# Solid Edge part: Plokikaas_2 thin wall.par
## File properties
Author: KULL
Template: Iso Metric Part.par
Last saved by: KULL
Revision: 9
Application: Solid Edge
Accuracy: 0,990
Face Style: Model Default
Fill Style: Normal
Coef. of Thermal Exp: 0.0
Thermal Conductivity: 0.0
Specific Heat: 0.0
Modulus of Elasticity: 0.0
Poisson's Ratio: 0.0
Yield Stress: 0.0
Ultimate Stress: 0.0
Elongation: 0.0
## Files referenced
..\..\Mootor_ASM_1.asm
hiplokk 2.par
lG:\Haapsalu Kolledz\Solid edge leong\Solid edge Sync practice\ROVER_Heiko_Kull_EKSAM\Mootor\Mootor_ASM_1.asm
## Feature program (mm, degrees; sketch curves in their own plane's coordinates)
pattern "unnamed Pattern 1"
pattern "unnamed Pattern 2"
Other named dimensions: "Pattern_1": XDirCount = 5; XDirSpacing = 18 mm | "Pattern_2": XDirCount = 5; XDirSpacing = 18 mm
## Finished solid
Body 1: sheet body, 1 face, 13 edges, 8 vertices.
  Faces by surface: plane 1
  Edges by curve: circle 9, line 4
Body 2: solid body, 256 faces, 478 edges, 216 vertices, 1 internal void.
  Faces by surface: plane 54, cylinder 52, torus 50, offset 40, spline 40, cone 20
  Edges by curve: circle 142, line 120, intersection 116, ellipse 40, curve on surface 30, spline 30
Bounding box of the edges (mm; curved faces can reach further): 96.000 x 29.454 x 27.888, from (-48, 15.1609, 37.8813) to (48, 44.6145, 65.7694).
Cylindrical faces by radius (mm): R0.7583 x10, R0.7983 x10, R3 x4, R3.04 x4, R5 x8, R5.04 x8, R7.96 x4, R8 x4
Conical faces (half-angle, radius in mm at the cone's reference point): 0.9869 deg R2.4867 x10, 0.9869 deg R2.5267 x10
Toroidal faces (ring radius, tube radius in mm): R2.1444 r0.4 x10, R2.1444 r0.44 x10, R2.582 r1.7841 x10, R2.582 r1.8241 x10, R3.3542 r4 x5, R3.3542 r4.04 x5
Planar faces by outward normal: +x 2, -x 2, oblique 50
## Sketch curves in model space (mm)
line (36, 34.3873, 57.1877) -> (-36, 34.3873, 57.1877)
line (36, 28.3292, 45.3007) -> (36, 41.2745, 52.7747)
line (36, 26.031, 47.2291) -> (36, 30.6273, 43.3724)
line (36, 26.031, 47.2291) -> (36, 37.0524, 60.3638)
line (36, 40.115, 43.2436) -> (-36, 40.115, 43.2436)
circle centre (-36, 40.115, 43.2436) radius 2
circle centre (-18, 40.115, 43.2436) radius 2
circle centre (0, 40.115, 43.2436) radius 2
circle centre (18, 40.115, 43.2436) radius 2
line (-42, 40.0885, 35.4334) -> (-30, 40.0885, 35.4334)
line (-24, 40.0885, 35.4334) -> (-12, 40.0885, 35.4334)
line (-6, 40.0885, 35.4334) -> (6, 40.0885, 35.4334)
line (12, 40.0885, 35.4334) -> (24, 40.0885, 35.4334)
line (30, 40.0885, 35.4334) -> (42, 40.0885, 35.4334)
line (48, 43.9453, 40.0297) -> (-48, 43.9453, 40.0297)
circle centre (-36, 43.9453, 40.0297) radius 2
circle centre (-18, 43.9453, 40.0297) radius 2
circle centre (0, 43.9453, 40.0297) radius 2
circle centre (18, 43.9453, 40.0297) radius 2
circle centre (36, 43.9453, 40.0297) radius 2
line (48, 21.2893, 49.9025) -> (48, 29.4872, 43.0236)
arc centre (40, 29.4872, 43.0236) radius 8 from (48, 29.4872, 43.0236) through (45.4899, 33.9448, 39.2833) to (40, 35.6155, 37.8813)
line (40, 35.6155, 37.8813) -> (-40, 35.6155, 37.8813)
arc centre (-40, 29.4872, 43.0236) radius 8 from (-40, 35.6155, 37.8813) through (-45.819, 33.6927, 39.4948) to (-48, 29.4872, 43.0236)
line (-48, 29.4872, 43.0236) -> (-48, 21.2893, 49.9025)
arc centre (-40, 21.2893, 49.9025) radius 8 from (-48, 21.2893, 49.9025) through (-45.4899, 16.8317, 53.6428) to (-40, 15.1609, 55.0448)
line (-40, 15.1609, 55.0448) -> (40, 15.1609, 55.0448)
arc centre (40, 21.2893, 49.9025) radius 8 from (40, 15.1609, 55.0448) through (45.819, 17.0838, 53.4313) to (48, 21.2893, 49.9025)
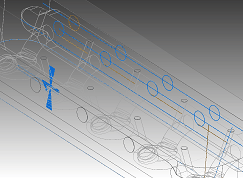
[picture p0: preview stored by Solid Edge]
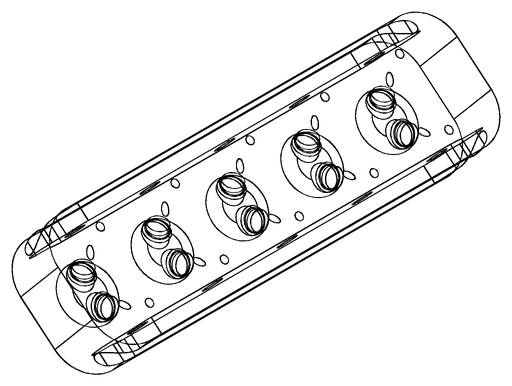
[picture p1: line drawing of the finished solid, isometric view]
